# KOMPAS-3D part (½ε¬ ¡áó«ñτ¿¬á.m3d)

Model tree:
1. Эскиз:1
2. Операция выдавливания:1
     Расстояние 1 = 0.2
3. Эскиз:2
4. Операция выдавливания:2
     Расстояние 1 = 3
5. Эскиз:3
6. Операция выдавливания:3
     Расстояние 1 = 0.2
7. Скругление:1
     Радиус = 1.2
8. Эскиз:4
9. Вырезать элемент выдавливания:1
     Расстояние 1 = 30.543
10. Эскиз:5
11. Операция выдавливания:4
     Расстояние 1 = 8
12. Эскиз:6
13. Операция выдавливания:5
     Расстояние 1 = 4
14. Эскиз:7
15. Вырезать элемент выдавливания:2
     Расстояние 1 = 5
16. Эскиз:8
17. Вырезать элемент выдавливания:3
     Расстояние 1 = 0.2

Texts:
  Сплав АЛ8  ГОСТ 1583-93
